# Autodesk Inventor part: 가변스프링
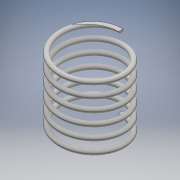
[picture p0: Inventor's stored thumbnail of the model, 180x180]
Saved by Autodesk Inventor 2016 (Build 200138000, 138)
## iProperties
Created: 2018-02
Part Number: 가변스프링
Material: 일반
Document SubType Name: Modeling
Designer: 605-11
Density: 1 g/cm^3
Appearance: 기본값
Author: 605-11
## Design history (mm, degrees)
sketch "스케치1"
  geometry: L1 (0, 0)-(20, 0); L2 (20, 0)-(20, 47.25); L3 (20, 47.25)-(0, 47.25); L4 (0, 47.25)-(0, 0); C1 r 1.5 at (20, 0)
  constraints: 8 end point, 2 parallel, 1 centre point, 1 coincident, 1 horizontal, 1 perpendicular
  dimensions: "d1" = 47.25 distance of L2.end L1.end (derived); "d2" = 40 diameter of L2 L4; "d3" = 3 diameter of C1
feature "코일1" sketch "스케치1" pitch "d4" = 10; turns "d6" = 6; dims "d5" = 47.25 (= d1), "d7" = 0, angle "d8" = 90 deg, angle "d9" = 90 deg, "d10" = 0, "d11" = 0
node "작업 평면1"
feature "분할1"
feature "분할2"
node "솔리드1"
